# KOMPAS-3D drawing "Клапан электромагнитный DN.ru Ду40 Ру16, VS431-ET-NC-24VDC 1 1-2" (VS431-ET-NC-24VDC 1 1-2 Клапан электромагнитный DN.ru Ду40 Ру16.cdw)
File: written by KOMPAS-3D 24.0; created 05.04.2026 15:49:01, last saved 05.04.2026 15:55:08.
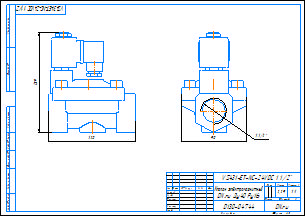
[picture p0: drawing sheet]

Document properties: c3d_UniqueCompID: ef56311e-7521-43dc-8291-0e6108b3d81d; Автор: artio; Класс точности: c; Знак неуказанной шероховатости: Шероховатость не задана; Рассекать на разрезах: Да; c3d_UniqueCompID: ef56311e-7521-43dc-8291-0e6108b3d81d; Автор: artio; Класс точности: c; Знак неуказанной шероховатости: Шероховатость не задана; Рассекать на разрезах: Да; c3d_UniqueCompID: ef56311e-7521-43dc-8291-0e6108b3d81d; Автор: artio; Класс точности: c; Знак неуказанной шероховатости: Шероховатость не задана; Рассекать на разрезах: Да; c3d_UniqueCompID: ef56311e-7521-43dc-8291-0e6108b3d81d; Автор: artio; Класс точности: c; Знак неуказанной шероховатости: Шероховатость не задана; Рассекать на разрезах: Да; Автор: artio; Форматы листов документа: A3; Полное имя файла: VS431-ET-NC-24VDC 1 1-2 Клапан электромагнитный DN.ru Ду40 Ру16.m3d; Масса: 2.285; Наименование: Клапан электромагнитный DN.ru Ду40 Ру16; Количество листов документа: 1; Примечание: D130-04744

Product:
- Body: Тело 1  | qty 1
    Масса: 3.859459
- Part/product: Клапан электромагнитный DN.ru Ду40 Ру16  | designation VS431-ET-NC-24VDC 1 1-2
    Масса: 2.285
    Раздел спецификации: Прочие изделия
    Примечание: D130-04744
    additional columns: ef56311e-7521-43dc-8291-0e6108b3d81d; artio; c; Шероховатость не задана; Да

Views: Вид 1, Спереди
Referenced files in C:\Users\artio\OneDrive\Рабочий стол\Клапан электромагнитный DN.ru\VS431\VS431-ET-NC\: VS431-ET-NC-24VDC 3-4 Клапан электромагнитный DN.ru Ду20 Ру16.m3d, VS431-ET-NC-24VDC 1 1-2 Клапан электромагнитный DN.ru Ду40 Ру16.m3d, VS431-ET-NC-24VDC 3-4 Клапан электромагнитный DN.ru Ду20 Ру16.cdw
Referenced files in C:\Users\artio\OneDrive\Рабочий стол\Клапан электромагнитный DN.ru\VS431\VS431-ET-NC\VS431-ET-NC-24VDC\Ду40\: VS431-ET-NC-24VDC 1 1-2 Клапан электромагнитный DN.ru Ду40 Ру16.m3d
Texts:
  VS431-ET-NC-24VDC 1 1-2
  Клапан электромагнитный
  DN.ru Ду40 Ру16
  VS431-ET-NC-24VDC 1 1/2"
  VS431-ET-NC-24VDC 1 1/2"-
  Клапан электромагнитный DN.ru Ду40 Ру16
  VS431-ET-NC-24VDC 1 1-2 Клапан электромагнитный DN.ru Ду40 Ру16
Dimensions and other numbers on the sheet: 0; 3; 2; 4; 90; 1 1/2"; 1:1; 1; 2,29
